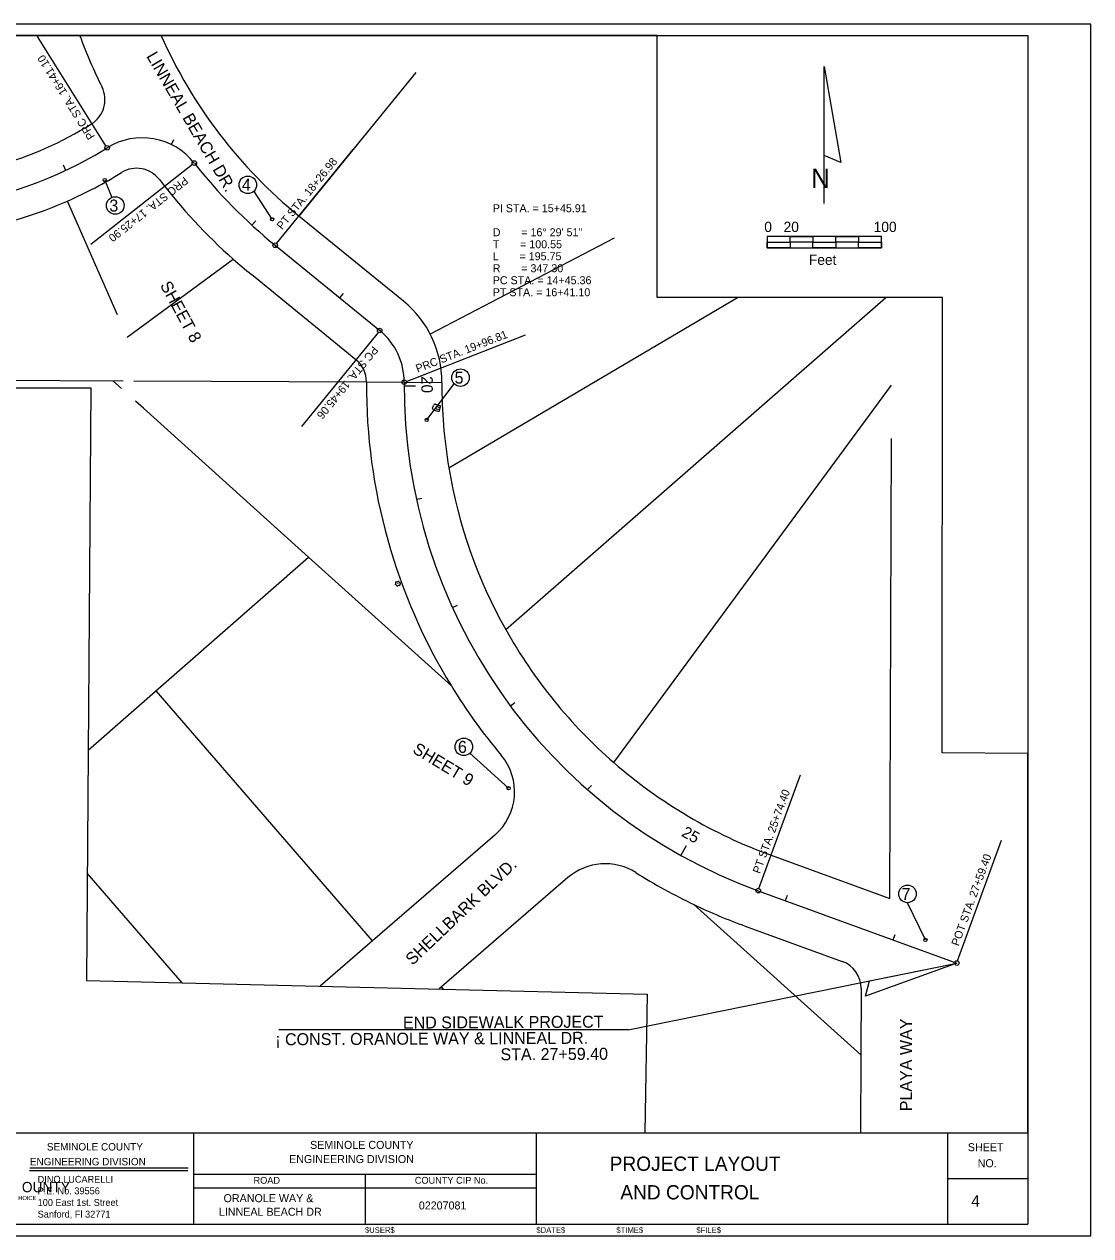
# Model space of a CAD drawing. Extents: x 508530 to 510180, y 1567639 to 1568699.
# Drawn here: x 509247 to 510180, y 1567639 to 1568699 of the extents above; entities that cross this region are included whole.
import ezdxf

# ---------------------------------------------------------------- set-up
doc = ezdxf.new("R2010")
doc.units = 0
for name, color, linetype in [('CLConst_dp', 7, 'Continuous'), ('CurveDataLabel_dp', 7, 'Continuous'), ('DrainMisc_ep', 7, 'Continuous'), ('GPKDrBack_dp', 7, 'Continuous'), ('GPKDrBottom_dp', 7, 'Continuous'), ('GPKDrCellIns_dp', 7, 'Continuous'), ('GPKDrFront_dp', 7, 'Continuous'), ('GPKDrPipe_dp', 7, 'Continuous'), ('LeaderLine_dp', 7, 'Continuous'), ('Logo_dp', 7, 'Continuous'), ('NonPlottingEle_dp', 7, 'Continuous'), ('NorthArw_dp', 7, 'Continuous'), ('PlotBorder_dp', 7, 'Continuous'), ('RWLine_ep', 7, 'Continuous'), ('Scale_dp', 7, 'Continuous'), ('SheetBorder_dp', 7, 'Continuous'), ('SheetLines_dp', 7, 'Continuous'), ('StationTicL_dp', 7, 'Continuous'), ('StationTicS_dp', 7, 'Continuous'), ('SubDivLine', 7, 'Continuous'), ('TextBLStation', 7, 'Continuous'), ('TextElevLabel', 7, 'Continuous'), ('TextMinor', 7, 'Continuous'), ('TextMisc', 7, 'Continuous'), ('TextPtLabel', 7, 'Continuous'), ('TextShtNo', 7, 'Continuous'), ('TreePine_ep', 7, 'Continuous')]:
    doc.layers.add(name, color=color, linetype=linetype)

msp = doc.modelspace()

# ---------------------------------------------------------------- linework, layer by layer
at = {"layer": 'CLConst_dp'}
for p, q in [((509466.6, 1568505.4), (509558.1, 1568430.8)), ((509889.3, 1567940.7), (510063.1, 1567877.4))]:
    msp.add_line(p, q, dxfattribs=at)
for centre, radius, start, end in [((509350.3, 1568541.4), 58, 38.24, 122.0065), ((509135.5, 1568885.1), 347.3, 269.7131, 302.0065), ((509757.2, 1568862), 460, 218.24, 230.8297), ((509521.5, 1568385.9), 58, 359.7094, 50.8297), ((510050.5, 1568383.2), 471, 179.7143, 249.9839)]:
    msp.add_arc(centre, radius, start, end, dxfattribs=at)
at = {"layer": 'CurveDataLabel_dp'}
for p, q in [((509318.5, 1568592.3), (509258.6, 1568688.2)), ((509467.9, 1568507), (509534.9, 1568589.3)), ((509394.3, 1568576.1), (509305.4, 1568506.1)), ((509556.9, 1568429.3), (509489.8, 1568346.9)), ((509581.4, 1568386.3), (509685.8, 1568426.9)), ((509889.9, 1567942.6), (509926.2, 1568042.2)), ((510063.8, 1567879.3), (510102.3, 1567984.9))]:
    msp.add_line(p, q, dxfattribs=at)
for centre in [(509319.6, 1568590.6), (509395.9, 1568577.3), (509466.6, 1568505.4), (509558.1, 1568430.8), (509579.5, 1568385.6), (509889.3, 1567940.7), (510063.1, 1567877.4)]:
    msp.add_circle(centre, 2, dxfattribs=at)
at = {"layer": 'DrainMisc_ep'}
for p, q in [((509607, 1568366.3), (509611.3, 1568365)), ((509604.4, 1568363), (509605.1, 1568365.3)), ((509609.8, 1568359.8), (509605.4, 1568361.2)), ((509609, 1568361.9), (509610.3, 1568361.5)), ((509609.6, 1568363.7), (509610.8, 1568363.3)), ((509611.3, 1568365), (509609.8, 1568359.8))]:
    msp.add_line(p, q, dxfattribs=at)
for centre, start, end in [((509606.5, 1568364.9), 72.7064, 162.7064), ((509605.8, 1568362.6), 162.7064, 252.7064)]:
    msp.add_arc(centre, 1.5, start, end, dxfattribs=at)
msp.add_ellipse((509609.2, 1568362.8), major_axis=(-2.23, 0.69), ratio=0.410714, start_param=4.697305, end_param=7.868996, dxfattribs=at)
at = {"layer": 'GPKDrBack_dp'}
msp.add_line((509610.6, 1568362.4), (509610.6, 1568362.4), dxfattribs=at)
at = {"layer": 'GPKDrBottom_dp'}
msp.add_line((509607, 1568363.5), (509607, 1568363.5), dxfattribs=at)
at = {"layer": 'GPKDrCellIns_dp'}
msp.add_line((509607, 1568363.5), (509607, 1568363.5), dxfattribs=at)
at = {"layer": 'GPKDrFront_dp'}
msp.add_line((509604.8, 1568364.2), (509604.8, 1568364.2), dxfattribs=at)
at = {"layer": 'GPKDrPipe_dp'}
msp.add_line((509604.8, 1568364.2), (509604.8, 1568364.2), dxfattribs=at)
at = {"layer": 'LeaderLine_dp'}
for p, q in [((510063.1, 1567877.4), (509983.3, 1567848.4)), ((509986.6, 1567861.9), (510063.1, 1567877.4)), ((509983.3, 1567848.4), (509986.6, 1567861.9))]:
    msp.add_line(p, q, dxfattribs=at)
at = {"layer": 'NonPlottingEle_dp'}
msp.add_lwpolyline([(508585.3, 1568380.7), (509305.4, 1568380.7), (509301.4, 1567862), (509792.2, 1567850.3), (509790, 1567728.8), (510125.3, 1567728.8), (510125.3, 1568060.8), (510050.1, 1568061.2), (510050.5, 1568459.6), (509800.8, 1568459.6), (509800.8, 1568688.8), (508585.3, 1568688.8)], close=True, dxfattribs=at)
at = {"layer": 'NorthArw_dp'}
msp.add_line((509947.1, 1568541.9), (509947.1, 1568661.9), dxfattribs=at)
msp.add_lwpolyline([(509947.1, 1568583.9), (509947.1, 1568661.9), (509961.5, 1568577.9)], close=True, dxfattribs=at)
at = {"layer": 'PlotBorder_dp'}
msp.add_lwpolyline([(508530.3, 1567638.8), (510180.3, 1567638.8), (510180.3, 1568698.8), (508530.3, 1568698.8)], close=True, dxfattribs=at)
at = {"layer": 'RWLine_ep'}
for p, q in [((509579, 1568456.4), (509487.4, 1568531)), ((509537.3, 1568405.3), (509445.8, 1568479.8)), ((509658.8, 1567989.4), (509551.7, 1567896.8)), ((509900.6, 1567971.7), (510004.5, 1567933.9)), ((509722.8, 1567952.2), (509612.3, 1567856.6)), ((509878, 1567909.7), (509962.8, 1567878.8)), ((509551.7, 1567896.8), (509506, 1567857.2)), ((509612.3, 1567856.6), (509610.1, 1567854.7)), ((509979.3, 1567855.2), (509979.1, 1567797)), ((509979.1, 1567797), (509978.8, 1567728.8))]:
    msp.add_line(p, q, dxfattribs=at)
for centre, radius, start, end in [((509757.2, 1568862), 493, 200.5752, 206.2723), ((509757.2, 1568862), 427, 203.9386, 230.8297), ((509292.7, 1568632.8), 25, 301.9158, 26.2723), ((509135.5, 1568885.1), 322.3, 269.7131, 301.9158), ((509135.5, 1568885.1), 372.3, 293.6661, 301.8895), ((509345.4, 1568547.8), 25, 37.3505, 121.8895), ((509757.2, 1568862), 493, 217.3505, 228.418), ((509135.5, 1568885.1), 372.3, 282.1234, 293.6661), ((509757.2, 1568862), 493, 228.418, 230.8297), ((509521.5, 1568385.9), 91, 359.7219, 50.8297), ((509521.5, 1568385.9), 25, 359.7219, 50.8297), ((510050.5, 1568383.2), 504, 179.7131, 211.5025), ((510050.5, 1568383.2), 438, 179.7131, 189.5372), ((510050.5, 1568383.2), 438, 189.5372, 209.2586), ((510050.5, 1568383.2), 438, 209.2586, 228.98), ((510050.5, 1568383.2), 504, 211.5025, 219.9984), ((509626.1, 1568027.2), 50, 310.8528, 39.9984), ((510050.5, 1568383.2), 438, 228.98, 249.9839), ((509755.5, 1567914.3), 50, 57.829, 130.8528), ((510050.5, 1568383.2), 504, 237.829, 244.4354), ((510050.5, 1568383.2), 504, 244.4354, 249.9836), ((509954.3, 1567855.3), 25, 359.8056, 69.9836)]:
    msp.add_arc(centre, radius, start, end, dxfattribs=at)
at = {"layer": 'Scale_dp'}
for p, q in [((509997.1, 1568513.2), (509897.1, 1568513.2)), ((509897.1, 1568513.2), (509897.1, 1568503.2)), ((509897.1, 1568503.2), (509997.1, 1568503.2)), ((509997.1, 1568503.2), (509997.1, 1568513.2))]:
    msp.add_line(p, q, dxfattribs=at)
for points in [[(509897.1, 1568503.2), (509897.1, 1568508.2), (509917.1, 1568508.2), (509917.1, 1568503.2)], [(509917.1, 1568508.2), (509917.1, 1568513.2), (509937.1, 1568513.2), (509937.1, 1568508.2)], [(509937.1, 1568503.2), (509937.1, 1568508.2), (509957.1, 1568508.2), (509957.1, 1568503.2)], [(509957.1, 1568508.2), (509957.1, 1568513.2), (509977.1, 1568513.2), (509977.1, 1568508.2)], [(509977.1, 1568503.2), (509977.1, 1568508.2), (509997.1, 1568508.2), (509997.1, 1568503.2)]]:
    msp.add_lwpolyline(points, close=True, dxfattribs=at)
at = {"layer": 'SheetBorder_dp'}
for p, q in [((508585.3, 1568688.8), (510125.3, 1568688.8)), ((510125.3, 1568688.8), (510125.3, 1567648.8)), ((508585.3, 1567728.8), (510125.3, 1567728.8)), ((508585.3, 1567648.8), (510125.3, 1567648.8))]:
    msp.add_line(p, q, dxfattribs=at)
at = {"layer": 'SheetLines_dp'}
for p, q in [((509395.3, 1567728.8), (509395.3, 1567648.8)), ((509695.3, 1567648.8), (509695.3, 1567728.8)), ((510055.3, 1567648.8), (510055.3, 1567728.8)), ((509395.3, 1567692.8), (509695.3, 1567692.8)), ((509545.3, 1567692.8), (509545.3, 1567648.8)), ((510055.3, 1567688.8), (510125.3, 1567688.8)), ((509395.3, 1567680.8), (509695.3, 1567680.8))]:
    msp.add_line(p, q, dxfattribs=at)
at = {"layer": 'StationTicL_dp'}
for p, q in [((509579.5, 1568382.4), (509589.5, 1568382.4)), ((509821.7, 1567971.6), (509826.5, 1567980.3))]:
    msp.add_line(p, q, dxfattribs=at)
at = {"layer": 'StationTicS_dp'}
for p, q in [((509375.9, 1568593.5), (509378.1, 1568598)), ((509283.5, 1568570.9), (509281.4, 1568575.5)), ((509446.2, 1568523.1), (509449.6, 1568526.8)), ((509523.2, 1568459.3), (509526.4, 1568463.2)), ((509590.3, 1568283.2), (509595.1, 1568284.2)), ((509621.7, 1568188.4), (509626.2, 1568190.5)), ((509672.4, 1568102.4), (509676.4, 1568105.4)), ((509740, 1568029.1), (509743.3, 1568032.8)), ((509913.3, 1567932), (509915, 1567936.7)), ((510007.3, 1567897.7), (510009, 1567902.4))]:
    msp.add_line(p, q, dxfattribs=at)
at = {"layer": 'SubDivLine'}
for p, q in [((509589.8, 1568656.6), (509487.4, 1568531)), ((509328.6, 1568444.5), (509284.9, 1568544.1)), ((509602.5, 1568427.9), (509763.4, 1568511.9)), ((509337.1, 1568425.1), (509430, 1568493.3)), ((509618.6, 1568310.7), (509871.3, 1568459.6)), ((509668.4, 1568169.2), (510001, 1568459.6)), ((508713.7, 1568389.9), (509333.6, 1568386.8)), ((509332.2, 1568380), (509324.6, 1568386.9)), ((509342.9, 1568386.8), (509546.5, 1568385.8)), ((509546.5, 1568385.8), (509612.5, 1568385.4)), ((509763, 1568052.8), (510005.9, 1568383.1)), ((509351.3, 1568362.8), (509344.3, 1568369.1)), ((509495.9, 1568232.5), (509351.3, 1568362.8)), ((510004.5, 1567933.9), (510005.9, 1568336.2)), ((509303, 1568063.7), (509495.9, 1568232.5)), ((509620.8, 1568119.9), (509495.9, 1568232.5)), ((509551.7, 1567896.8), (509362.4, 1568115.7)), ((509385.2, 1567860), (509302.1, 1567956.1)), ((509833, 1567928.6), (509979.1, 1567797)), ((509614, 1567854.6), (509612.3, 1567856.6))]:
    msp.add_line(p, q, dxfattribs=at)
at = {"layer": 'TextMisc'}
for p, q in [((509317.5, 1568562.4), (509323.7, 1568547.2)), ((509463.9, 1568528.1), (509448.1, 1568552.9)), ((509599.2, 1568352.6), (509623.3, 1568384.2)), ((509670.9, 1568030.3), (509637.1, 1568061.1)), ((510035.6, 1567897.7), (510019.9, 1567930.2)), ((509775.4, 1567819.1), (510063.1, 1567877.4)), ((509775.4, 1567819.1), (509469.9, 1567819.1)), ((509251.9, 1567698.2), (509390.5, 1567698.2)), ((509251.7, 1567696), (509390.3, 1567696))]:
    msp.add_line(p, q, dxfattribs=at)
for centre, radius in [((509317.5, 1568562.4), 1.44), ((509442.7, 1568558.3), 7.69), ((509326.7, 1568540.2), 7.69), ((509463.9, 1568528.1), 1.44), ((509628.8, 1568389.6), 7.69), ((509599.2, 1568352.6), 1.44), ((509631.7, 1568066.6), 7.69), ((509670.9, 1568030.3), 1.44), ((510019.9, 1567937.9), 7.69), ((510035.6, 1567897.7), 1.44)]:
    msp.add_circle(centre, radius, dxfattribs=at)
at = {"layer": 'TreePine_ep'}
msp.add_line((509573.9, 1568209.3), (509573.9, 1568209.3), dxfattribs=at)
msp.add_line((509573.9, 1568209.3), (509573.9, 1568209.3), dxfattribs=at)
msp.add_circle((509573.9, 1568209.3), 0.05, dxfattribs=at)
msp.add_circle((509573.9, 1568209.3), 0.05, dxfattribs=at)
for centre, start, end in [((509570.3, 1568210), 309.5678, 26.9322), ((509570.3, 1568210), 309.5678, 26.9322), ((509571.4, 1568206.5), 9.5678, 86.9322), ((509571.4, 1568206.5), 9.5678, 86.9322), ((509572.7, 1568212.8), 249.5678, 326.9322), ((509572.7, 1568212.8), 249.5678, 326.9322), ((509575.1, 1568205.7), 69.5678, 146.9322), ((509575.1, 1568205.7), 69.5678, 146.9322), ((509576.4, 1568212.1), 189.5678, 266.9322), ((509576.4, 1568212.1), 189.5678, 266.9322), ((509577.6, 1568208.5), 129.5678, 206.9322), ((509577.6, 1568208.5), 129.5678, 206.9322)]:
    msp.add_arc(centre, 2, start, end, dxfattribs=at)

# ---------------------------------------------------------------- texts
at = {"layer": 'CurveDataLabel_dp'}
for s, rotation, p in [('PRC STA. 16+41.10', 122.0065, (509309.2, 1568600.6)), ('PT STA. 18+26.98', 50.8297, (509472.7, 1568518.5)), ('PRC STA. 17+25.90', 218.24, (509387, 1568565.9)), ('PRC STA. 19+96.81', 21.2359, (509591.3, 1568393.9)), ('PC STA. 19+45.06', 230.8297, (509552, 1568417.8)), ('PT STA. 25+74.40', 69.9839, (509890.8, 1567955.1)), ('POT STA. 27+59.40', 69.9836, (510064.6, 1567891.8))]:
    msp.add_text(s, height=7, rotation=rotation, dxfattribs=at).set_placement(p)
at = {"layer": 'Logo_dp'}
for s, height, p in [('EMINOLE       OUNTY', 9, (509167.4, 1567676.9)), ("LORIDA'S      ATURAL     HOICE", 3.6, (509184.3, 1567670))]:
    msp.add_text(s, height=height, dxfattribs=at).set_placement(p)
at = {"layer": 'NonPlottingEle_dp'}
for s, p in [('PI STA. = 15+45.91', (509657, 1568534.3)), ('D       = 16%%d 29\' 51"', (509657, 1568513.3)), ('T       = 100.55', (509657, 1568502.8)), ('L       = 195.75', (509657, 1568492.3)), ('R       = 347.30', (509657, 1568481.8)), ('PC STA. = 14+45.36', (509657, 1568471.3)), ('PT STA. = 16+41.10', (509657, 1568460.8))]:
    msp.add_text(s, height=7, dxfattribs=at).set_placement(p)
at = {"layer": 'NorthArw_dp'}
msp.add_text('N', height=16.8, dxfattribs=at).set_placement((509935.7, 1568555.5))
at = {"layer": 'Scale_dp'}
for s, p in [('0', (509894.6, 1568517)), ('20', (509911.5, 1568517)), ('100', (509990.3, 1568517)), ('Feet', (509933.6, 1568488.2))]:
    msp.add_text(s, height=9, dxfattribs=at).set_placement(p)
at = {"layer": 'TextBLStation'}
for s, rotation, p in [('20', 270.1025, (509594.5, 1568391)), ('25', 330.9325, (509821.4, 1567988.9))]:
    msp.add_text(s, height=10, rotation=rotation, dxfattribs=at).set_placement(p)
at = {"layer": 'TextElevLabel'}
msp.add_text('114.92', height=0.5, dxfattribs=at).set_placement((509574.4, 1568209))
at = {"layer": 'TextMinor'}
for s, p in [('$USER$', (509545.2, 1567641.3)), ('$DATE$', (509695.2, 1567641.3)), ('$TIME$', (509765.2, 1567641.3)), ('$FILE$', (509835.2, 1567641.3))]:
    msp.add_text(s, height=5, rotation=360, dxfattribs=at).set_placement(p)
at = {"layer": 'TextMisc'}
for s, height, rotation, p in [('LINNEAL BEACH DR.', 10.5, 300.3425, (509353.6, 1568670.9)), ('4', 10.5, 359.7131, (509437.5, 1568553.1)), ('3', 10.5, 359.7131, (509321.5, 1568534.9)), ('SHEET 8', 10.5, 298.5342, (509365.6, 1568470.5)), ('5', 10.5, 359.7131, (509623.6, 1568384.4)), ('SHEET 9', 10.5, 328.8511, (509586.1, 1568061.9)), ('6', 10.5, 359.7131, (509626.5, 1568061.3)), ('SHELLBARK BLVD.', 10.5, 43.5724, (509586.8, 1567874.9)), ('7', 10.5, 359.7131, (510014.7, 1567932.6)), ('END SIDEWALK PROJECT', 10.5, 0.2869, (509578.4, 1567820)), ('PLAYA WAY', 10.5, 90, (510023.8, 1567747.7)), ('¡ CONST. ORANOLE WAY & LINNEAL DR.', 10.5, 0.2869, (509466.7, 1567805.4)), ('STA. 27+59.40', 10.5, 0.2869, (509663.8, 1567792.3)), ('SEMINOLE COUNTY', 7, 360, (509497.2, 1567714.8)), ('SHEET', 7, 359.8607, (510072.7, 1567712.8)), ('ENGINEERING DIVISION', 7, 360, (509478.8, 1567702.4)), ('NO.', 7, 359.8607, (510081.3, 1567698.8)), ('ROAD', 6, 360, (509447.7, 1567684.3)), ('COUNTY CIP No.', 6, 360, (509588.8, 1567684.3)), ('ORANOLE WAY & ', 7, 360, (509421.5, 1567668.2)), ('   02207081   ', 7, 360, (509584.5, 1567661.8)), (' LINNEAL BEACH DR', 7, 360, (509414.8, 1567656.3))]:
    msp.add_text(s, height=height, rotation=rotation, dxfattribs=at).set_placement(p)
for s, height, p in [('SEMINOLE COUNTY', 6.5, (509266.9, 1567713.4)), ('     PROJECT LAYOUT     ', 12.5, (509736.1, 1567695.6)), ('ENGINEERING DIVISION', 6.5, (509252, 1567700.4)), ('DINO LUCARELLI', 6, (509258.8, 1567685.2)), ('P.E. No. 39556', 6, (509258.8, 1567675.1)), ('      AND CONTROL       ', 12.5, (509740.8, 1567670.6)), ('100 East 1st. Street', 6, (509258.8, 1567664.9)), ('Sanford, Fl 32771', 6, (509258.8, 1567654.7))]:
    msp.add_text(s, height=height, dxfattribs=at).set_placement(p)
at = {"layer": 'TextPtLabel'}
msp.add_text('TREEPI835', height=0.5, dxfattribs=at).set_placement((509574.4, 1568209.8))
at = {"layer": 'TextShtNo'}
msp.add_text('  4   ', height=10, dxfattribs=at).set_placement((510068.3, 1567664.3))

doc.saveas('drawing.dxf')
